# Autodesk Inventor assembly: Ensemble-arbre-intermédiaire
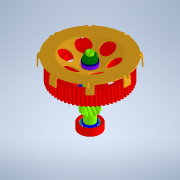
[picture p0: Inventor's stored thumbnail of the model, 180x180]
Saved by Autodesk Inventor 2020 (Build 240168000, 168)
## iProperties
Created: 2020-09
Part Number: Ensemble-arbre-intermédiaire
Document SubType Name: Assembly
Designer: Bruno
Author: Bruno
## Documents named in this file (9)
- D:\Téléchargements-2016-17\scoot_elec\Ensemble-arbre-intermédiaire.iam
- D:\Téléchargements-2016-17\scoot_elec\pièces à assembler\ARBRE PRIMAIRE.ipt
- D:\Téléchargements-2016-17\scoot_elec\pièces à assembler\ROULEMENT 6203\Roulement 6203.iam
- D:\Téléchargements-2016-17\scoot_elec\pièces à assembler\POULIE CRANTÉE RÉCEPTRICE.ipt
- D:\Téléchargements-2016-17\scoot_elec\pièces à assembler\COURONNE DU CAPTEUR.ipt
- D:\Téléchargements-2016-17\scoot_elec\pièces à assembler\ENTRETOISE.ipt
- D:\Téléchargements-2016-17\scoot_elec\pièces à assembler\Rondelle plate M10.ipt
- D:\Téléchargements-2016-17\scoot_elec\pièces à assembler\ECROU À EMBASE M10.ipt
- D:\Téléchargements-2016-17\scoot_elec\pièces à assembler\ROULEMENT 6201\Roulement 6201.iam
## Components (8 placed, 8 different names)
1. ARBRE PRIMAIRE:1 — Placage:1, Placage:2, Placage:4, Placage:5, Placage:7, Placage:9, Placage:10, Placage:11, Placage:12
2. POULIE CRANTÉE RÉCEPTRICE:1 — Placage:1, Placage:2, Placage:3
3. COURONNE DU CAPTEUR:1 — Placage:3, Placage:4, Placage:6
4. ENTRETOISE:1 — Placage:5, Placage:6, Placage:8
5. Rondelle plate M10:1 — Placage:7, Placage:8, Logement:1
6. ECROU À EMBASE M10:1 — Logement:1
7. Roulement 6203:1 [sub-assembly] — Placage:9, Placage:10
8. Roulement 6201:1 [sub-assembly] — Placage:11, Placage:12
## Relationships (13: Mate 12, Insert 1)
- Placage:1 [Mate]: ARBRE PRIMAIRE:1 ↔ POULIE CRANTÉE RÉCEPTRICE:1
- Placage:2 [Mate]: ARBRE PRIMAIRE:1 ↔ POULIE CRANTÉE RÉCEPTRICE:1
- Placage:3 [Mate]: POULIE CRANTÉE RÉCEPTRICE:1 ↔ COURONNE DU CAPTEUR:1
- Placage:4 [Mate]: ARBRE PRIMAIRE:1 ↔ COURONNE DU CAPTEUR:1
- Placage:5 [Mate]: ARBRE PRIMAIRE:1 ↔ ENTRETOISE:1
- Placage:6 [Mate]: COURONNE DU CAPTEUR:1 ↔ ENTRETOISE:1
- Placage:7 [Mate]: ARBRE PRIMAIRE:1 ↔ Rondelle plate M10:1
- Placage:8 [Mate]: ENTRETOISE:1 ↔ Rondelle plate M10:1
- Logement:1 [Insert]: Rondelle plate M10:1 ↔ ECROU À EMBASE M10:1
- Placage:9 [Mate]: ARBRE PRIMAIRE:1 ↔ Roulement 6203:1
- Placage:10 [Mate]: ARBRE PRIMAIRE:1 ↔ Roulement 6203:1
- Placage:11 [Mate]: ARBRE PRIMAIRE:1 ↔ Roulement 6201:1
- Placage:12 [Mate]: ARBRE PRIMAIRE:1 ↔ Roulement 6201:1
